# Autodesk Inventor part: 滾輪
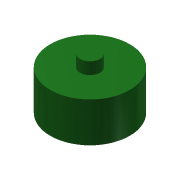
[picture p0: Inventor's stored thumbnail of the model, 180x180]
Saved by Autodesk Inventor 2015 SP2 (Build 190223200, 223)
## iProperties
Created: 2020-03
Part Number: 滾輪
Material: 一般
Document SubType Name: Modeling
Designer: Kuan-Lun Hsu
Density: 1 g/cm^3
Appearance: 平滑 - 深森林綠
Mass: 3.2594 g
Surface Area: 13.5088 cm^2
Volume: 3.2594 cm^3
Author: Kuan-Lun Hsu
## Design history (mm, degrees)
sketch "草圖1"
  geometry: C1 r 10 at (0, 0); 1 further point
  constraints: 1 centre point, 1 coincident
  dimensions: "d0" = 20 diameter of C1
extrude "擠出1" new body sketch "草圖1" stored distance "d1" = 10; taper "d2" = 0 deg
sketch "草圖2"
  geometry: C1 r 2.5 at (0, 0); 1 further point
  constraints: 1 centre point, 1 coincident
  dimensions: "d3" = 5 diameter of C1
extrude "擠出2" join sketch "草圖2" distance "d4" = 3; taper "d5" = 0 deg
mirror "鏡射1"
node "實體1"
